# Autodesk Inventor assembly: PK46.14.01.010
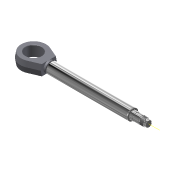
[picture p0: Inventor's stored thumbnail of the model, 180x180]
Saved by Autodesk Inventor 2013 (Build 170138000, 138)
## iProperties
Shininess: 64.0
Length Units: 11269
Angle Units: 11279
Time Units: 11290
Mass Units: 11283
Length Display Precision: 3
Angle Display Precision: 2
Compacted: True
Created: 2004-11
Part Number: PK46.14.01.010
Document SubType Name: Assembly
Designer: ELarisa
Manufacturer: Standard
Standards Organization: Custom
Density: 0.0
Volumn: 0.0
Area: 0.0
PropertySet Name: Model Information
Control State: 0
Master: False
Checked Out: False
Checked Out Date: 2008-10-15
Last Check In Date: 2008-10-15
Author: ELarisa
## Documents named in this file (3)
- C:\Product Design Suite 2013 Test Drive\Model Based Documentation\Workspace\Assemblies\PK46.14.01.010.iam
- C:\Product Design Suite 2013 Test Drive\Model Based Documentation\Workspace\Parts\PK46.14.01.001.ipt
- C:\Product Design Suite 2013 Test Drive\Model Based Documentation\Workspace\Parts\PK46.14.01.008.ipt
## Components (2 placed, 2 different names)
1. PK46.14.01.001:1 — Insert:1, Angle:1
2. PK46.14.01.008:1 — Insert:1, Angle:1
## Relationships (2: Insert 1, Angle 1)
- Insert:1: PK46.14.01.001:1 ↔ PK46.14.01.008:1
- Angle:1: PK46.14.01.001:1 ↔ PK46.14.01.008:1
